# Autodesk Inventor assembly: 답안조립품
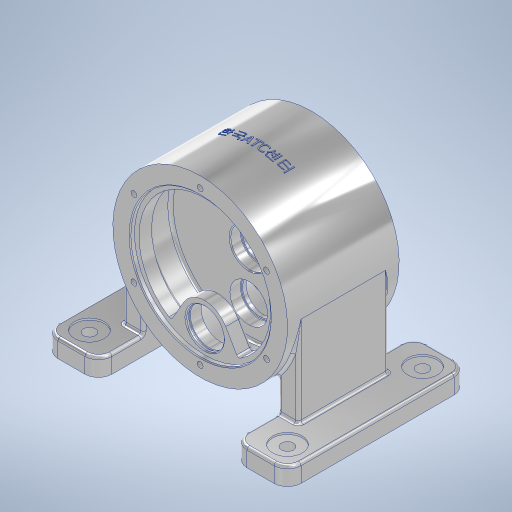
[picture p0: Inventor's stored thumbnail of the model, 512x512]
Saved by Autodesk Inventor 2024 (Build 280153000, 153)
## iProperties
Created: 2025-12
Part Number: 답안조립품
Document SubType Name: Assembly
Designer: Eud07
Author: Eud07
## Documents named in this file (2)
- C:\Users\Eud07\Desktop\751203V1002\답안조립품.iam
- C:\Users\Eud07\Desktop\751203V1002\본체.ipt
